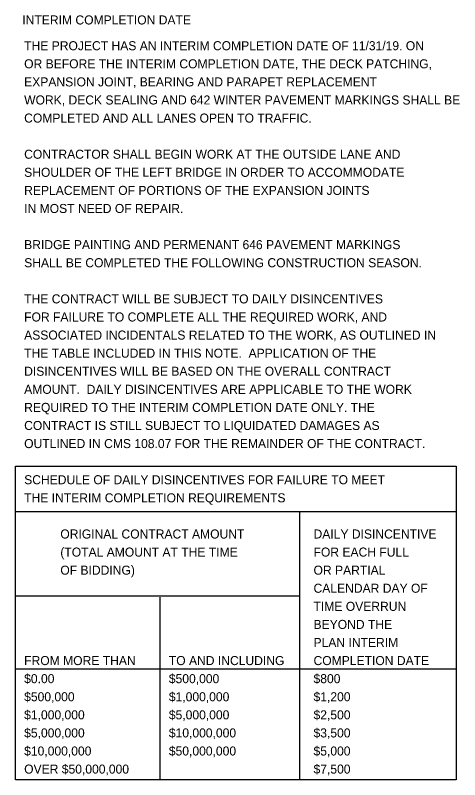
# Model space of a CAD drawing. Extents: x -15.3 to 74.8, y -11.5 to 47.6.
# Drawn here: x -9.08 to -2.2, y 35.77 to 47.6 of the extents above; entities that cross this region are included whole.
import ezdxf

# ---------------------------------------------------------------- set-up
doc = ezdxf.new("R2010")
doc.units = 0
doc.layers.add('SH_Text', color=7, linetype='Continuous')

msp = doc.modelspace()

# ---------------------------------------------------------------- linework, layer by layer
at = {"layer": 'SH_Text'}
for p, q in [((-9.061, 39.919), (-2.253, 39.919)), ((-4.678, 39.907), (-4.678, 35.767)), ((-9.076, 38.612), (-4.678, 38.612)), ((-6.836, 38.594), (-6.836, 35.767)), ((-9.073, 37.486), (-2.253, 37.486))]:
    msp.add_line(p, q, dxfattribs=at)
msp.add_lwpolyline([(-9.073, 40.624), (-2.253, 40.624), (-2.253, 35.767), (-9.073, 35.767)], close=True, dxfattribs=at)

# ---------------------------------------------------------------- texts
for s, p in [('INTERIM COMPLETION DATE', (-8.967, 47.461)), ('THE PROJECT HAS AN INTERIM COMPLETION DATE OF 11/31/19. ON', (-8.939, 47.062)), ('OR BEFORE THE INTERIM COMPLETION DATE, THE DECK PATCHING,', (-8.939, 46.782)), ('EXPANSION JOINT, BEARING AND PARAPET REPLACEMENT', (-8.939, 46.502)), ('WORK, DECK SEALING AND 642 WINTER PAVEMENT MARKINGS SHALL BE', (-8.939, 46.222)), ('COMPLETED AND ALL LANES OPEN TO TRAFFIC.', (-8.939, 45.942)), ('CONTRACTOR SHALL BEGIN WORK AT THE OUTSIDE LANE AND', (-8.939, 45.382)), ('SHOULDER OF THE LEFT BRIDGE IN ORDER TO ACCOMMODATE', (-8.939, 45.102)), ('REPLACEMENT OF PORTIONS OF THE EXPANSION JOINTS', (-8.939, 44.822)), ('IN MOST NEED OF REPAIR.', (-8.939, 44.542)), ('BRIDGE PAINTING AND PERMENANT 646 PAVEMENT MARKINGS', (-8.939, 43.982)), ('SHALL BE COMPLETED THE FOLLOWING CONSTRUCTION SEASON.', (-8.939, 43.702)), ('THE CONTRACT WILL BE SUBJECT TO DAILY DISINCENTIVES', (-8.939, 43.142)), ('FOR FAILURE TO COMPLETE ALL THE REQUIRED WORK, AND', (-8.939, 42.862)), ('ASSOCIATED INCIDENTALS RELATED TO THE WORK, AS OUTLINED IN', (-8.939, 42.582)), ('THE TABLE INCLUDED IN THIS NOTE.  APPLICATION OF THE', (-8.939, 42.302)), ('DISINCENTIVES WILL BE BASED ON THE OVERALL CONTRACT', (-8.939, 42.022)), ('AMOUNT.  DAILY DISINCENTIVES ARE APPLICABLE TO THE WORK', (-8.939, 41.742)), ('REQUIRED TO THE INTERIM COMPLETION DATE ONLY. THE', (-8.939, 41.462)), ('CONTRACT IS STILL SUBJECT TO LIQUIDATED DAMAGES AS', (-8.939, 41.182)), ('OUTLINED IN CMS 108.07 FOR THE REMAINDER OF THE CONTRACT. ', (-8.939, 40.902)), ('SCHEDULE OF DAILY DISINCENTIVES FOR FAILURE TO MEET', (-8.939, 40.342)), ('THE INTERIM COMPLETION REQUIREMENTS', (-8.939, 40.062)), ('ORIGINAL CONTRACT AMOUNT', (-8.379, 39.502)), ('DAILY DISINCENTIVE ', (-4.459, 39.502)), ('(TOTAL AMOUNT AT THE TIME', (-8.379, 39.222)), ('FOR EACH FULL', (-4.459, 39.222)), ('OF BIDDING)', (-8.379, 38.942)), ('OR PARTIAL', (-4.459, 38.942)), ('CALENDAR DAY OF', (-4.459, 38.662)), ('TIME OVERRUN', (-4.459, 38.382)), ('BEYOND THE', (-4.459, 38.102)), ('PLAN INTERIM', (-4.459, 37.822)), ('FROM MORE THAN', (-8.939, 37.542)), ('TO AND INCLUDING', (-6.699, 37.542)), ('COMPLETION DATE', (-4.459, 37.542)), ('$0.00', (-8.939, 37.262)), ('$500,000', (-6.699, 37.262)), ('$800', (-4.459, 37.262)), ('$500,000', (-8.939, 36.982)), ('$1,000,000', (-6.699, 36.982)), ('$1,200', (-4.459, 36.982)), ('$1,000,000', (-8.939, 36.702)), ('$5,000,000', (-6.699, 36.702)), ('$2,500', (-4.459, 36.702)), ('$5,000,000', (-8.939, 36.422)), ('$10,000,000', (-6.699, 36.422)), ('$3,500', (-4.459, 36.422)), ('$10,000,000', (-8.939, 36.142)), ('$50,000,000', (-6.699, 36.142)), ('$5,000', (-4.459, 36.142)), ('OVER $50,000,000', (-8.939, 35.862)), ('$7,500', (-4.459, 35.862))]:
    msp.add_text(s, height=0.14, dxfattribs=at).set_placement(p)

doc.saveas('drawing.dxf')
